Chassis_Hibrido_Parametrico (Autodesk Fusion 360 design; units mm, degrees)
part number: 2026-10-27-14-45-14-391
part number: 2026-10-27-14-47-23-326
part number: 2026-10-27-14-47-50-998
part number: 2026-10-27-14-47-52-763
part number: 2026-10-27-14-47-55-088
parameter "comprimento" = 1706
parameter "largura" = 1146
parameter "altura" = 460
parameter "d_furo_susp" = 101.6
parameter "x_furo_susp" = 657
parameter "z_furo_susp" = 218
parameter "folga_furo_susp" = 40
parameter "espessura_furo_susp" = 26
parameter "ang_chamfro_susp" = 30
parameter "tamanho_susp" = 181.6 (= "d_furo_susp + 2 * folga_furo_susp")
parameter "dist_susp" = 521.1667 (= "x_furo_susp - tamanho_susp / 2 - chanfro_susp")
parameter "chanfro_susp" = 45.0333 (= "espessura_furo_susp / tan(ang_chamfro_susp)")
parameter "comp_tras" = 194
parameter "degrau_tras" = 16.5
parameter "recuo_rampa_tras" = 38
parameter "ang_rampa_tras" = 20.56
parameter "alt_aresta_tras" = 384.9877 (= "altura - degrau_tras - ( comp_tras - recuo_rampa_tras ) * tan(ang_rampa_tras)")
parameter "base_torre" = 320
parameter "alt_torre" = 304
parameter "alt_torre_frente" = 279.5 (= "alt_torre - queda_topo_torre")
parameter "alt_ombro_torre" = 191.5
parameter "x_ombro_torre" = 159.5
parameter "recuo_ombro_torre" = 8.5
parameter "dif_topo_torre" = 88 (= "alt_torre_frente - alt_ombro_torre")
parameter "larg_tras_torre" = 158
parameter "dist_suporte_braco" = 70
parameter "larg_suporte_braco" = 220
parameter "alt_suporte_braco" = 16
parameter "base_suporte_braco" = 40
parameter "esp_suporte_braco" = 210
parameter "esp_parede_braco" = 20 (= "esp_suporte_braco * rel_parede_braco")
parameter "d_furo_ponta" = 110
parameter "parede_ponta" = 24
parameter "r_ext_ponta" = 79 (= "d_furo_ponta / 2 + parede_ponta")
parameter "x_ponta" = 68
parameter "y_ponta" = 16
parameter "margem_ponta" = 5
parameter "comp_ponta" = 152 (= "x_ponta + r_ext_ponta + margem_ponta")
parameter "esp_ponta_frente" = 63
parameter "esp_ponta_tras" = 45
parameter "ang_ponta_tras" = 97
parameter "offset_topo_ponta" = 6
parameter "ang_ponta_planta" = 100
parameter "furo_ponta" = 20 (= "d_furo_ponta * 0.0909090909090909 * 2")
parameter "comp_box" = 320.88 (= "largura * 0.28")
parameter "alt_box" = 170.016 (= "altura * 0.3696")
parameter "topo_box" = 214.6366 (= "comp_box * 0.6689")
parameter "alt_tras_box" = 105.0019 (= "alt_box * 0.6176")
parameter "larg_box" = 305.0328 (= "comprimento * 0.1788")
parameter "x_box" = -50
parameter "dist_torres" = 810 (= "largura - 2 * larg_tras_torre - 20 mm")
parameter "meio_viga" = 380 (= "( dist_torres - 50 mm ) / 2")
parameter "reto_sup_viga" = 130 (= "meio_viga * 130 / 380")
parameter "reto_inf_viga" = 105 (= "meio_viga * 105 / 380")
parameter "esp_fundo_braco" = 4.955 comment "fundo do suporte do braco"
parameter "queda_topo_torre" = 24.5 comment "diferenca entre alt_torre e alt_torre_frente"
derived_base_feature "Derived Base Feature1" bodies "camara", "camara (Assembly_Perseverance)"
derived_base_feature "Derived Base Feature2" bodies "lente_dir", "lente_dir (Assembly_Perseverance)"
derived_base_feature "Derived Base Feature3" bodies "sensor_esq", "sensor_esq (Assembly_Perseverance)"
derived_base_feature "Derived Base Feature4" bodies "lente_esq", "lente_esq (Assembly_Perseverance)"
derived_base_feature "Derived Base Feature5" bodies "sensor_dir (Assembly_Perseverance)"
derived_base_feature "Derived Base Feature6" bodies "Body1 (Assembly_Perseverance)"
sketch "Sketch1" plane through (0, 0, 0) normal (0, 0, 1) x axis (1, 0, 0)
  line L1 (-853, 573) -> (853, 573)
  line L2 (-853, -573) -> (-853, 573)
  line L3 (853, -573) -> (-853, -573)
  line L4 (853, 573) -> (853, -573)
  line L5 (-853, -573) -> (853, 573)
  line L6 (853, -573) -> (-853, 573)
  point P6 (0, 0)
  point P1 (0, 0)
  point P4 (-853, -573)
  point P5 (853, -573)
  point P3 (-853, 573)
  horizontal L1
  perpendicular L1 L2
  parallel L1 L3
  parallel L2 L4
  coincident L5 P6
  coincident L6 P6
  coincident P1 P6
  dimension "d1" distance P4 P5 = 1706 (= "comprimento")
  dimension "d2" distance P3 P4 = 1146 (= "largura")
extrude "Extrude1" new body sketch "Sketch1" profile of L1 L2 L3 L4 along normal blind 460 (= "altura")
sketch "Sketch2" plane through (0, 0, 460) normal (0, 0, 1) x axis (-1, 0, 0)
  line L1 (-853, -573) -> (-853, 573)
  line L2 (853, -573) -> (-853, -573)
  line L3 (853, 573) -> (853, -573)
  line L4 (-853, 573) -> (853, 573)
  line L5 (331.8333, 573) -> (853, 573)
  line L6 (286.8, 599) -> (331.8333, 573)
  line L7 (105.2, 599) -> (286.8, 599)
  line L8 (105.2, 573) -> (105.2, 599)
  line L9 (105.2, 573) -> (331.8333, 573)
  point P5 (853, 573)
  point P6 (853, 573)
  point P7 (331.8333, 573)
  point P10 (105.2, 573)
  point P8 (286.8, 599)
  point P9 (105.2, 599)
  coincident P5 P6
  coincident L4 P7
  parallel L4 L7
  coincident L4 P10
  perpendicular L4 L8
  dimension "d5" distance P6 P7 = 521.1667 (= "dist_susp")
  dimension "d6" distance P7 P8 = 45.0333 (= "chanfro_susp")
  dimension "d7" distance L7 L9 = 26 (= "espessura_furo_susp")
  dimension "d8" distance P8 P9 = 181.6 (= "tamanho_susp")
extrude "Extrude2" add sketch "Sketch2" profile of L4 L6 L7 L8 L9 no distance stored
sketch "Sketch3" plane through (0, -573, 0) normal (0, -1, 0) x axis (1, 0, 0)
  line L1 (-105.2, 0) -> (-105.2, 460)
  line L2 (853, 0) -> (-105.2, 0)
  line L3 (853, 460) -> (853, 0)
  line L4 (-105.2, 460) -> (853, 460)
  line L5 (1047, 460) -> (853, 460)
  line L6 (1047, 75.0123) -> (1047, 460)
  line L7 (891, 16.5) -> (1047, 75.0123)
  line L8 (853, 16.5) -> (891, 16.5)
  line L9 (853, 16.5) -> (853, 460)
  point P5 (853, 460)
  point P6 (853, 460)
  point P10 (853, 16.5)
  point P7 (1047, 460)
  point P8 (1047, 75.0123)
  point P4 (853, 0)
  point P9 (891, 16.5)
  coincident P5 P6
  perpendicular L3 L5
  perpendicular L5 L6
  coincident L3 P10
  perpendicular L3 L8
  dimension "d8" distance P5 = 181.6 (= "tamanho_susp")
  dimension "d11" distance P6 P7 = 194 (= "comp_tras")
  dimension "d12" distance P7 P8 = 384.9877 (= "alt_aresta_tras")
  dimension "d13" distance P4 L8 = 16.5 (= "degrau_tras")
  dimension "d14" distance P9 P10 = 38 (= "recuo_rampa_tras")
extrude "Extrude3" add sketch "Sketch3" profile of L3 L5 L6 L7 L8 L9 no distance stored
sketch "Sketch4" plane through (0, -573, 0) normal (0, -1, 0) x axis (1, 0, 0)
  line L1 (-105.2, 0) -> (-105.2, 460)
  line L2 (853, 0) -> (-105.2, 0)
  line L3 (853, 16.5) -> (853, 0)
  line L4 (-105.2, 460) -> (1047, 460)
  line L5 (1047, 764) -> (1047, 460)
  line L6 (895, 739.5) -> (1047, 764)
  line L7 (895, 651.5) -> (895, 739.5)
  line L8 (886.5, 651.5) -> (895, 651.5)
  line L9 (727, 460) -> (886.5, 651.5)
  line L10 (727, 460) -> (1047, 460)
  line L11 (891, 16.5) -> (853, 16.5)
  line L12 (1047, 75.0123) -> (891, 16.5)
  line L13 (1047, 460) -> (1047, 75.0123)
  point P6 (1047, 460)
  point P7 (1047, 460)
  point P12 (727, 460)
  point P13 (1047, 460)
  point P8 (1047, 764)
  point P11 (886.5, 651.5)
  point P10 (895, 651.5)
  point P9 (895, 739.5)
  coincident P6 P7
  perpendicular L4 L5
  parallel L5 L7
  perpendicular L7 L8
  coincident L4 P12
  coincident P6 P13
  dimension "d17" distance P7 P8 = 304 (= "alt_torre")
  dimension "d18" distance P12 P13 = 320 (= "base_torre")
  dimension "d19" distance P11 P12 = 159.5 (= "x_ombro_torre")
  dimension "d20" distance L8 L10 = 191.5 (= "alt_ombro_torre")
  dimension "d21" distance P10 P11 = 8.5 (= "recuo_ombro_torre")
  dimension "d22" distance P9 P10 = 88 (= "dif_topo_torre")
extrude "Extrude4" add sketch "Sketch4" profile of L4 L5 L6 L7 L8 L9 L10 to an object
mirror "Mirror1" mirrorStitchTolerance 0.1
mirror "Mirror2" mirrorStitchTolerance 0.1
mirror "Mirror3" mirrorStitchTolerance 0.1
sketch "Sketch6" plane through (0, 573, 0) normal (0, 1, 0) x axis (-1, 0, 0)
  line L1 (105.2, 460) -> (105.2, 0)
  line L2 (-727, 460) -> (105.2, 460)
  line L3 (-886.5, 651.5) -> (-727, 460)
  line L4 (-895, 651.5) -> (-886.5, 651.5)
  line L5 (-895, 739.5) -> (-895, 651.5)
  line L6 (-1047, 764) -> (-895, 739.5)
  line L7 (-1047, 75.0123) -> (-1047, 764)
  line L8 (-891, 16.5) -> (-1047, 75.0123)
  line L9 (-853, 16.5) -> (-891, 16.5)
  line L10 (-853, 0) -> (-853, 16.5)
  line L11 (105.2, 0) -> (-853, 0)
  line L12 (-1047, 651.5) -> (-895, 651.5)
  point P6 (-895, 651.5)
  point P13 (-895, 651.5)
  point P14 (-1047, 651.5)
  coincident P6 P13
  coincident L7 P14
  perpendicular L7 L12
extrude "Extrude6" add sketch "Sketch6" profile of L5 L6 L7 L12 along normal blind 10
sketch "Sketch7" plane through (0, 415, 0) normal (0, -1, 0) x axis (1, 0, 0)
  line L1 (1047, 764) -> (1047, 75.0123)
  line L2 (895, 739.5) -> (1047, 764)
  line L3 (895, 651.5) -> (895, 739.5)
  line L4 (886.5, 651.5) -> (895, 651.5)
  line L5 (727, 460) -> (886.5, 651.5)
  line L6 (853, 460) -> (727, 460)
  line L7 (1047, 651.5) -> (895, 651.5)
  line L8 (853, 16.5) -> (853, 460)
  line L9 (891, 16.5) -> (853, 16.5)
  line L10 (1047, 75.0123) -> (891, 16.5)
  point P6 (895, 651.5)
  point P9 (895, 651.5)
  point P10 (1047, 651.5)
  coincident P6 P9
  coincident L1 P10
  perpendicular L1 L7
extrude "Extrude7" add sketch "Sketch7" profile of L1 L2 L3 L7 along normal blind 10
sketch "Sketch8" plane through (1047, 0, 0) normal (1, 0, 0) x axis (0, 1, 0)
  line L1 (405, 764) -> (583, 764)
  line L2 (405, 651.5) -> (405, 764)
  line L3 (415, 651.5) -> (405, 651.5)
  line L4 (415, 75.0123) -> (415, 651.5)
  line L5 (573, 651.5) -> (573, 75.0123)
  line L6 (583, 651.5) -> (573, 651.5)
  line L7 (583, 764) -> (583, 651.5)
  line L8 (573, 651.5) -> (415, 651.5)
  line L9 (573, 75.0123) -> (415, 75.0123)
  point P5 (415, 651.5)
  point P10 (415, 651.5)
  point P8 (573, 651.5)
  point P11 (573, 651.5)
  coincident P5 P10
  coincident P8 P11
extrude "Extrude8" add sketch "Sketch8" profile of L1 L2 L3 L6 L7 L8 along normal blind 10
mirror "Mirror4" mirrorStitchTolerance 0.1
sketch "Sketch9" plane through (0, 405, 0) normal (0, -1, 0) x axis (1, 0, 0)
  line L1 (1057, 651.5) -> (895, 651.5)
  line L2 (1057, 764) -> (1057, 651.5)
  line L3 (1047, 764) -> (1057, 764)
  line L4 (895, 739.5) -> (1047, 764)
  line L5 (895, 651.5) -> (895, 739.5)
  line L6 (934.6634, 666.5679) -> (910.38, 733.2861)
  line L7 (916.0182, 735.3382) -> (910.38, 733.2861)
  line L8 (895, 739.5) -> (910.38, 733.2861)
  line L9 (895, 733.2861) -> (910.38, 733.2861)
  line L10 (940.3016, 668.62) -> (916.0182, 735.3382)
  line L11 (934.6634, 666.5679) -> (940.3016, 668.62)
  line L12 (1025.8136, 699.7439) -> (1001.5302, 766.462)
  line L13 (1001.5302, 766.462) -> (995.892, 764.4099)
  line L14 (1020.1755, 697.6917) -> (995.892, 764.4099)
  line L15 (1020.1755, 697.6917) -> (1025.8136, 699.7439)
  line L16 (1023.2485, 689.2486) -> (1020.1755, 697.6917)
  line L17 (1028.8867, 691.3007) -> (1023.2485, 689.2486)
  line L18 (1025.8136, 699.7439) -> (1028.8867, 691.3007)
  point P6 (895, 739.5)
  point P10 (895, 739.5)
  point P11 (895, 733.2861)
  point P7 (910.38, 733.2861)
  point P9 (916.0182, 735.3382)
  point P8 (934.6634, 666.5679)
  point P16 (1020.1755, 697.6917)
  point P17 (1023.2485, 689.2486)
  point P18 (1028.8867, 691.3007)
  perpendicular L6 L7
  coincident P6 P10
  coincident L5 P11
  perpendicular L5 L9
  perpendicular L7 L10
  perpendicular L10 L11
  perpendicular L15 L16
  perpendicular L16 L17
  dimension "d43" distance P7 P9 = 6
  dimension "d44" distance L5 P7 = 15.38
  dimension "d45" angle L8 L9 = 22
  dimension "d46" angle L6 L9 = 110
  dimension "d47" distance P7 P8 = 71
  dimension "d60" distance P16 P17 = 8.985
  dimension "d61" distance P17 P18 = 6
  dimension "d54" R-Pattern1-uDistance = -91
  dimension "d55" R-Pattern1-vDistance = 0
extrude "Extrude9" add sketch "Sketch9" profile of L4 L6 L7 L10 L11 L12 L14 L15 L16 L17 L18 along normal blind 20
mirror "Mirror5" mirrorStitchTolerance 0.1
fillet "Fillet2" radius 15 15 15
work_plane "WorkPlane1" ExtraOffset 0
sketch "Sketch11" plane through (-783, 0, 0) normal (-1, 0, 0) x axis (0, -1, 0)
  line L1 (-793, 460) -> (-573, 16)
  line L2 (-573, 460) -> (-793, 460)
  line L3 (-613, 16) -> (-573, 16)
  line L4 (-613, 96.7273) -> (-613, 16)
  line L5 (-573, 16) -> (-573, 460)
  line L6 (-573, 460) -> (573, 460)
  line L7 (573, 0) -> (-573, 0)
  point P5 (-613, 96.7273)
  point P7 (-573, 460)
  point P8 (-573, 460)
  point P2 (-573, 16)
  point P4 (-613, 16)
  point P3 (-793, 460)
  coincident L1 P5
  perpendicular L3 L4
  perpendicular L3 L5
  coincident P7 P8
  horizontal L2
  vertical L5
  dimension "d111" distance P2 P4 = 40 (= "base_suporte_braco")
  dimension "d147" distance P2 L7 = 16 (= "alt_suporte_braco")
  dimension "d148" distance P3 P8 = 220 (= "larg_suporte_braco")
extrude "Extrude16" new body sketch "Sketch11" profile of L1 L2 L5 no distance stored
work_plane "WorkPlane2" AlongDistance 200 (= "larg_suporte_braco - esp_parede_braco") ExtraOffset 0
sketch "Sketch12" plane through (0, 773, 0) normal (0, 1, 0) x axis (1, 0, 0)
  line L1 (-783, -460) -> (-783, -16)
  line L2 (-573, -460) -> (-783, -460)
  line L3 (-573, -16) -> (-573, -460)
  line L4 (-593, -16) -> (-593, -36)
  line L5 (-763, -16) -> (-763, -36)
  line L6 (-783, -16) -> (-573, -16)
  line L7 (-763, -440) -> (-763, -36)
  line L8 (-593, -440) -> (-763, -440)
  line L9 (-593, -36) -> (-593, -440)
  line L10 (-763, -36) -> (-593, -36)
  point P9 (-593, -36)
  point P13 (-593, -36)
  point P10 (-593, -16)
  point P6 (-763, -36)
  point P12 (-763, -36)
  point P11 (-763, -16)
  coincident P9 P13
  coincident P10 L6
  vertical L4
  coincident P6 P12
  coincident P11 L6
  vertical L5
extrude "Extrude17" cut sketch "Sketch12" profile of L9 L7 L8 L4 L5 L6 L10 no distance stored
mirror "Mirror9" mirrorStitchTolerance 0.1
combine "Combine1"
work_plane "WorkPlane3" AlongDistance -6 ExtraOffset 0
sketch "Sketch13" plane through (0, 577, 0) normal (0, 1, 0) x axis (1, 0, 0)
  line L1 (1209, -758) -> (1057, -758)
  line L2 (1214.4841, -713.3354) -> (1209, -758)
  line L3 (1057, -695) -> (1214.4841, -713.3354)
  line L4 (1057, -764) -> (1057, -651.5)
  point P2 (1057, -758)
  point P5 (1057, -695)
  point P3 (1209, -758)
  point P4 (1214.4841, -713.3354)
  point P7 (1057, -764)
  horizontal L1
  coincident P2 L4
  coincident P5 L4
  dimension "d124" distance P2 P5 = 63 (= "esp_ponta_frente")
  dimension "d125" distance P2 P3 = 152 (= "comp_ponta")
  dimension "d127" distance P3 P4 = 45 (= "esp_ponta_tras")
  dimension "d128" angle L1 L2 = 97 (= "ang_ponta_tras")
  dimension "d151" distance L1 P7 = 6 (= "offset_topo_ponta")
extrude "Extrude18" add sketch "Sketch13" no distance stored
sketch "Sketch14" plane through (0, 0, 758) normal (0, 0, 1) x axis (-1, 0, 0)
  line L1 (-1057, -577) -> (-1209, -577)
  line L2 (-1209, -419) -> (-1057, -419)
  line L3 (-1209, -577) -> (-1209, -419)
  line L4 (-1144.71, -434.4656) -> (-1057, -419)
  line L5 (-1057, -577) -> (-1117.6904, -587.7014)
  line L6 (-1117.6904, -587.7014) -> (-1144.71, -434.4656)
  line L7 (-2763, -419) -> (-1057, -419)
  line L8 (-2763, -1723) -> (-2763, -419)
  line L9 (-1057, -1723) -> (-2763, -1723)
  line L10 (-1057, -577) -> (-1057, -1723)
  line L11 (-1057, -419) -> (-1057, -577)
  line L12 (-1057, -405) -> (-1057, -583)
  arc A1 centre (-1131.2002, -511.0835) radius 77.7998 clockwise from (-1117.6904, -587.7014) to (-1144.71, -434.4656)
  point P4 (-1057, -419)
  point P6 (-1057, -419)
  point P3 (-1057, -577)
  point P10 (-1057, -577)
  point P14 (-1057, -577)
  point P13 (-1057, -1723)
  point P11 (-2763, -419)
  coincident P4 P6
  tangent L4 A1
  coincident P3 P10
  tangent A1 L5
  perpendicular L4 L6
  tangent L3 A1
  perpendicular L7 L8
  perpendicular L8 L9
  coincident P3 P14
  perpendicular L1 L10
  horizontal L7
  dimension "d152" angle L4 L12 = 100
  dimension "d229" distance P13 P14 = 1146 (= "largura")
  dimension "d230" distance P6 P11 = 1706 (= "comprimento")
extrude "Extrude19" cut sketch "Sketch14" profile of L1 L2 L3 L4 A1 L5 L7 L8 L9 L10 L12 no distance stored
extrude "Extrude20" add sketch "Sketch14" profile of L1 A1 L5 to an object
sketch "Sketch15" plane through (0, 0, 758) normal (0, 0, 1) x axis (-1, 0, 0)
  line L1 (-1144.71, -434.4656) -> (-1057, -419)
  line L2 (-1057, -577) -> (-1117.6904, -587.7014)
  line L3 (-1057, -419) -> (-1057, -577)
  arc A1 centre (-1131.2002, -511.0835) radius 77.7998 clockwise from (-1117.6904, -587.7014) to (-1144.71, -434.4656)
  circle C1 centre (-1131.2002, -511.0835) radius 55
  concentric A1 C1
  dimension "d136" diameter C1 = 110 (= "d_furo_ponta")
extrude "Extrude21" cut sketch "Sketch15" profile of C1 no distance stored
fillet "Fillet3" radius 10 (= "furo_ponta / 2")
mirror "Mirror8" mirrorStitchTolerance 0.1
sketch "Sketch18" plane through (0, 0, 758) normal (0, 0, 1) x axis (-1, 0, 0)
  line L1 (-1144.71, -434.4656) -> (-1057, -419)
  line L2 (-1057, -577) -> (-1117.6904, -587.7014)
  line L3 (-1057, -419) -> (-1057, -577)
  line L4 (-1021.2002, -511.0835) -> (-1131.2002, -511.0835)
  line L5 (-1186.2002, -415.8207) -> (-1131.2002, -511.0835)
  line L6 (-1186.2002, -606.3463) -> (-1131.2002, -511.0835)
  line L7 (-1201.2582, -426.2786) -> (-1182.7994, -452.8569)
  line L8 (-1169.6144, -408.009) -> (-1155.8263, -437.284)
  line L9 (-1182.7994, -569.3101) -> (-1201.2582, -595.8884)
  line L10 (-1155.8263, -584.883) -> (-1169.6144, -614.158)
  circle C1 centre (-1131.2002, -511.0835) radius 110
  circle C2 centre (-1186.2002, -415.8207) radius 18.3333
  circle C3 centre (-1186.2002, -606.3463) radius 18.3333
  circle C4 centre (-1021.2002, -511.0835) radius 18.3333
  circle C5 centre (-1131.2002, -511.0835) radius 55
  arc A1 centre (-1131.2002, -511.0835) radius 77.7998 clockwise from (-1117.6904, -587.7014) to (-1144.71, -434.4656)
  point P6 (-1131.2002, -511.0835)
  point P7 (-1131.2002, -511.0835)
  point P8 (-1021.2002, -511.0835)
  point P9 (-1186.2002, -415.8207)
  point P10 (-1186.2002, -606.3463)
  point P11 (-1186.2002, -415.8207)
  point P12 (-1186.2002, -606.3463)
  point P13 (-1021.2002, -511.0835)
  point P15 (-1201.2582, -426.2786)
  point P17 (-1169.6144, -408.009)
  point P18 (-1201.2582, -595.8884)
  point P20 (-1169.6144, -614.158)
  point P21 (-1155.8263, -584.883)
  point P19 (-1182.7994, -569.3101)
  point P14 (-1182.7994, -452.8569)
  point P16 (-1155.8263, -437.284)
  concentric C1 C5
  coincident P6 P7
  coincident C1 P8
  horizontal L4
  coincident C1 P9
  coincident C1 P10
  coincident P9 P11
  coincident P10 P12
  coincident P8 P13
  coincident C2 P15
  coincident C1 P15
  tangent C2 L7
  coincident C2 P17
  coincident C1 P17
  tangent C2 L8
  coincident C1 P18
  coincident C3 P18
  tangent C3 L9
  coincident C1 P20
  coincident C3 P20
  tangent C3 L10
  coincident P21 A1
  coincident P19 A1
  coincident P14 A1
  coincident P16 A1
  dimension "d153" diameter C1 = 220 (= "d_furo_ponta * 2")
  dimension "d154" angle L4 L5 = 120
  dimension "d155" angle L4 L6 = 120
  dimension "d225" diameter C3 = 36.6667 (= "d_furo_ponta / 3")
  dimension "d226" diameter C2 = 36.6667 (= "d_furo_ponta / 3")
  dimension "d227" diameter C4 = 36.6667 (= "d_furo_ponta / 3")
extrude "Extrude24" add sketch "Sketch18" profile of C1 C2 C3 C4 L7 L8 L9 L10 against normal blind 20
extrude "Extrude25" add sketch "Sketch18" profile of C1 C2 C3 C4 along normal blind 15
sketch "Sketch19" plane through (0, -599, 0) normal (0, -1, 0) x axis (1, 0, 0)
  line L1 (-286.8, 0) -> (-286.8, 460)
  line L2 (-105.2, 0) -> (-286.8, 0)
  line L3 (-105.2, 460) -> (-105.2, 0)
  line L4 (-853, 460) -> (-853, 0)
  line L5 (-286.8, 460) -> (-105.2, 460)
  circle C1 centre (-196, 218) radius 50.8
  point P6 (-196, 218)
  dimension "d160" diameter C1 = 101.6 (= "d_furo_susp")
  dimension "d161" distance L2 P6 = 218 (= "z_furo_susp")
  dimension "d162" distance P6 L4 = 657 (= "x_furo_susp")
extrude "Extrude26" cut sketch "Sketch19" profile of C1 against normal blind 97
work_plane "WorkPlane4"
mirror "Mirror10" mirrorStitchTolerance 0.1
sketch "Sketch20" plane through (0, 0, 460) normal (0, 0, 1) x axis (-1, 0, 0)
  line L1 (783, -573) -> (783, -793)
  line L2 (853, -573) -> (783, -573)
  line L3 (853, 573) -> (853, -573)
  line L4 (783, 573) -> (853, 573)
  line L5 (783, 793) -> (783, 573)
  line L6 (573, 793) -> (783, 793)
  line L7 (573, 573) -> (573, 793)
  line L8 (331.8333, 573) -> (573, 573)
  line L9 (286.8, 599) -> (331.8333, 573)
  line L10 (105.2, 599) -> (286.8, 599)
  line L11 (105.2, 573) -> (105.2, 599)
  line L12 (-727, 573) -> (105.2, 573)
  line L13 (-727, 415) -> (-727, 573)
  line L14 (-853, 415) -> (-727, 415)
  line L15 (-853, -415) -> (-853, 415)
  line L16 (-727, -415) -> (-853, -415)
  line L17 (-727, -573) -> (-727, -415)
  line L18 (105.2, -573) -> (-727, -573)
  line L19 (105.2, -599) -> (105.2, -573)
  line L20 (286.8, -599) -> (105.2, -599)
  line L21 (331.8333, -573) -> (286.8, -599)
  line L22 (573, -573) -> (331.8333, -573)
  line L23 (573, -793) -> (573, -573)
  line L24 (783, -793) -> (573, -793)
  line L25 (-250.7128, 160) -> (-185.3, 573)
  line L26 (-458.4, 0) -> (-277.0131, 119.2505)
  line L27 (-1.2664, 50) -> (-85.3, 573)
  line L28 (0, 0) -> (0, 34.1359)
  line L29 (-458.4, 0) -> (0, 0)
  line L30 (0, 0) -> (0, -34.1359)
  line L31 (-1.2664, -50) -> (-85.3, -573)
  line L32 (-250.7128, -160) -> (-185.3, -573)
  line L33 (-458.4, 0) -> (-277.0131, -119.2505)
  arc A1 centre (-100, 34.1359) radius 100 clockwise from (-1.2664, 50) to (0, 34.1359)
  arc A2 centre (-309.9741, 169.3861) radius 60 clockwise from (-250.7128, 160) to (-277.0131, 119.2505)
  arc A3 centre (-100, -34.1359) radius 100 clockwise from (0, -34.1359) to (-1.2664, -50)
  arc A4 centre (-309.9741, -169.3861) radius 60 clockwise from (-277.0131, -119.2505) to (-250.7128, -160)
  point P26 (-185.3, 573)
  point P28 (-85.3, 573)
  point P1 (0, 0)
  point P29 (0, 0)
  point P41 (-185.3, -573)
  point P27 (-458.4, 0)
  point P45 (-458.4, 0)
  point P40 (-85.3, -573)
  point P37 (0, 0)
  point P30 (-1.2664, 50)
  point P39 (-1.2664, -50)
  point P31 (0, 34.1359)
  point P36 (0, -34.1359)
  point P33 (-250.7128, 160)
  point P42 (-250.7128, -160)
  point P34 (-277.0131, 119.2505)
  point P44 (-277.0131, -119.2505)
  coincident L12 P26
  coincident L12 P28
  coincident P1 P29
  vertical L28
  horizontal L29
  tangent L27 A1
  tangent L28 A1
  tangent L25 A2
  tangent L26 A2
  symmetric P26 L29 P41
  symmetric P27 L29 P45
  symmetric P28 L29 P40
  symmetric P29 L29 P37
  symmetric L29 P30 P39
  symmetric L29 P31 P36
  symmetric L29 A1 A3
  symmetric L29 P33 P42
  symmetric L29 P34 P44
  symmetric L29 A2 A4
  dimension "d167" radius A1 = 100
  dimension "d168" radius A2 = 60
  dimension "d228" distance P26 P28 = 100 (= "comprimento / 17.06")
  dimension "d77" distance L3 P40 = 938.3 (= "comprimento * 0.55")
  dimension "d78" distance L18 P39 = 523 (= "largura / 2 - 50 mm")
  dimension "d79" distance P41 P42 = 413 (= "largura / 2 - 160 mm")
  dimension "d80" distance P37 P45 = 458.4 (= "largura / 2.5")
  dimension "d81" angle L12 L25 = 99
extrude "Extrude27" add sketch "Sketch20" profile of L12 L18 L25 L26 L27 L28 A1 A2 L30 A3 L31 L32 A4 L33 along normal blind 10
extrude "Extrude28" add of existing geometry blind 8.828
fillet "Fillet6" radius 25
sketch "Sketch1" plane through (0, 0, 0) normal (0, 1, 0) x axis (1, 0, 0)
  line L1 (320.88, 0) -> (0, 0)
  line L2 (320.88, -105.0019) -> (320.88, 0)
  line L3 (214.6366, -170.016) -> (320.88, -105.0019)
  line L4 (0, -170.016) -> (214.6366, -170.016)
  line L5 (0, 0) -> (0, -170.016)
  point P1 (0, 0)
  point P2 (0, 0)
  point P6 (0, -170.016)
  point P5 (214.6366, -170.016)
  point P3 (320.88, 0)
  point P4 (320.88, -105.0019)
  coincident P1 P2
  horizontal L1
  perpendicular L1 L2
  parallel L1 L4
  vertical L5
  dimension "d1_1" distance P2 P6 = 170.016 (= "alt_box")
  dimension "d2_1" distance P5 P6 = 214.6366 (= "topo_box")
  dimension "d3_1" distance P2 P3 = 320.88 (= "comp_box")
  dimension "d4_1" distance P3 P4 = 105.0019 (= "alt_tras_box")
extrude "Extrude1" new body sketch "Sketch1" along normal blind 305.0328 (= "larg_box") named "d5_1"
work_plane "WorkPlane1" AlongDistance -25 named "d7_1" ExtraOffset 0 named "d8_1"
sketch "Sketch2" plane through (0, 280.0328, 0) normal (0, 1, 0) x axis (1, 0, 0)
  line L1 (0, 0) -> (0, -170.016)
  line L2 (-55, -170.016) -> (0, -170.016)
  line L3 (0, -115.016) -> (-55, -170.016)
  point P2 (0, -170.016)
  point P4 (0, -170.016)
  point P6 (0, -115.016)
  point P5 (-55, -170.016)
  coincident P2 P4
  perpendicular L1 L2
  coincident L1 P6
  dimension "d9_1" distance P4 P5 = 55
  dimension "d10_1" distance P4 P6 = 55
extrude "Extrude2" new body sketch "Sketch2" against normal blind 55 named "d11_1"
work_plane "WorkPlane2" AlongDistance 55 named "d13_1" ExtraOffset 0 named "d14_1"
sketch "Sketch3" plane through (-55, 0, 0) normal (-1, 0, 0) x axis (0, -1, 0)
  line L1 (-280.0328, 115.016) -> (-280.0328, 170.016)
  line L2 (-225.0328, 115.016) -> (-280.0328, 115.016)
  line L3 (-225.0328, 170.016) -> (-225.0328, 115.016)
  line L4 (-280.0328, 170.016) -> (-225.0328, 170.016)
  line L5 (-275.0328, 120.016) -> (-275.0328, 165.016)
  line L6 (-230.0328, 120.016) -> (-275.0328, 120.016)
  line L7 (-230.0328, 165.016) -> (-230.0328, 120.016)
  line L8 (-275.0328, 165.016) -> (-230.0328, 165.016)
  dimension "d15_1" = -5
extrude "Extrude3" cut sketch "Sketch3" profile of L5 L6 L7 L8 against normal blind 50 named "d16_1"
sketch "Sketch4" plane through (0, 0, 170.016) normal (0, 0, 1) x axis (-1, 0, 0)
  line L1 (55, -280.0328) -> (0, -280.0328)
  line L2 (55, -225.0328) -> (55, -280.0328)
  line L3 (0, -225.0328) -> (55, -225.0328)
  line L4 (0, -280.0328) -> (0, -225.0328)
  line L5 (0, -225.0328) -> (55, -280.0328)
  circle C1 centre (27.5, -252.5328) radius 25
  point P3 (55, -280.0328)
  point P6 (55, -280.0328)
  point P5 (0, -225.0328)
  point P7 (0, -225.0328)
  point P8 (27.5, -252.5328)
  coincident P3 P6
  coincident P5 P7
  midpoint L5 P8
  dimension "d18_1" diameter C1 = 50
extrude "Extrude4" new body sketch "Sketch4" profile of C1 along normal blind 5 named "d19_1"
sketch "Sketch5" plane through (0, 0, 175.016) normal (0, 0, 1) x axis (-1, 0, 0)
  circle C1 centre (27.5, -252.5328) radius 25
  circle C2 centre (27.5, -252.5328) radius 15
  concentric C1 C2
  dimension "d21_1" diameter C2 = 30
extrude "Extrude5" add sketch "Sketch5" profile of C2 along normal blind 10 named "d22_1"
sketch "Sketch6" plane through (0, 0, 185.016) normal (0, 0, 1) x axis (-1, 0, 0)
  circle C1 centre (27.5, -252.5328) radius 15
  circle C2 centre (27.5, -252.5328) radius 6.25
  concentric C1 C2
  dimension "d24_1" diameter C2 = 12.5
extrude "Extrude6" add sketch "Sketch6" profile of C2 along normal blind 70 named "d25_1"
chamfer "Chamfer1" distance 2 named "d27_1"
sketch "Sketch7" plane through (0, 0, 0) normal (0, 0, -1) x axis (1, 0, 0)
  line L1 (0, 0) -> (320.88, 0)
  line L2 (0, -305.0328) -> (0, 0)
  line L3 (320.88, -305.0328) -> (0, -305.0328)
  line L4 (320.88, 0) -> (320.88, -305.0328)
  line L5 (273.38, -305.0328) -> (320.88, -305.0328)
  line L6 (273.38, -277.5328) -> (273.38, -305.0328)
  line L7 (320.88, -277.5328) -> (273.38, -277.5328)
  line L8 (320.88, -305.0328) -> (320.88, -277.5328)
  point P5 (320.88, -305.0328)
  point P6 (320.88, -305.0328)
  point P7 (273.38, -305.0328)
  point P9 (320.88, -277.5328)
  horizontal L5
  vertical L6
  horizontal L7
  vertical L8
  coincident P5 P6
  dimension "d28_1" distance P6 P7 = 47.5
  dimension "d29_1" distance P6 P9 = 27.5
  dimension "d13_3" angle P7 = 162 (= "180 deg - 18 deg")
extrude "Extrude7" cut sketch "Sketch7" profile of L3 L4 L5 L6 L7 L8 against normal blind 230 named "d30_1"
fillet "Fillet1" radius 2
sketch "Sketch3" plane through (0, 0, 0) normal (0, 1, 0) x axis (1, 0, 0)
  line L1 (-102, 0) -> (0, 0)
  line L2 (-102, -209.7618) -> (-102, 0)
  line L3 (0, -242) -> (0, 0)
  arc A1 centre (0, -159.5) radius 82.5 clockwise from (0, -242) to (-58.3197, -217.853)
  arc A2 centre (-102, 0) radius 220 clockwise from (-62.7463, -216.4697) to (-91.5238, -219.7504)
  arc A3 centre (-61.8542, -221.3895) radius 5 clockwise from (-62.7463, -216.4697) to (-58.3197, -217.853)
  arc A4 centre (-92, -209.7618) radius 10 clockwise from (-91.5238, -219.7504) to (-102, -209.7618)
  point P1 (0, 0)
  point P2 (0, 0)
  point P3 (-102, 0)
  point P6 (-102, 0)
  point P4 (0, -242)
  coincident P1 P2
  horizontal L1
  perpendicular L1 L2
  perpendicular A1 L3
  vertical L3
  perpendicular L2 A2
  tangent A1 A3
  tangent A2 A3
  tangent A2 A4
  tangent L2 A4
  coincident P3 P6
  dimension "d10_2" distance P2 P3 = 102 (= "d_furo_ponta - 8 mm")
  dimension "d13_2" distance P2 P4 = 242 (= "d_furo_ponta * 2.2")
  dimension "d73" radius A1 = 82.5 (= "d_furo_ponta * 0.75")
  dimension "d74" radius A2 = 220 (= "d_furo_ponta * 2")
  dimension "d75" radius A3 = 5
  dimension "d76" radius A4 = 10
revolve "Revolve1" sketch "Sketch3" AlongAngle 360 named "d15_2"
sketch "Sketch4" plane through (0, 0, 0) normal (0, 0, -1) x axis (1, 0, 0)
  line L1 (-51, 88.3346) -> (0, 0)
  line L2 (-88.3346, 51) -> (0, 0)
  line L3 (-102, 0) -> (0, 0)
  line L4 (-79.6743, 46) -> (-88.3346, 51)
  line L5 (-46, 79.6743) -> (-51, 88.3346)
  line L6 (-46, -79.6743) -> (-51, -88.3346)
  line L7 (-79.6743, -46) -> (-88.3346, -51)
  line L8 (79.6743, -46) -> (88.3346, -51)
  line L9 (46, -79.6743) -> (51, -88.3346)
  line L10 (46, 79.6743) -> (51, 88.3346)
  line L11 (79.6743, 46) -> (88.3346, 51)
  circle C1 centre (0, 0) radius 102
  arc A1 centre (0, 0) radius 102 clockwise from (-88.3346, 51) to (-51, 88.3346)
  arc A2 centre (0, 0) radius 92 clockwise from (-79.6743, 46) to (-46, 79.6743)
  arc A3 centre (0, 0) radius 102 clockwise from (-51, -88.3346) to (-88.3346, -51)
  arc A4 centre (0, 0) radius 92 clockwise from (-46, -79.6743) to (-79.6743, -46)
  arc A5 centre (0, 0) radius 102 clockwise from (88.3346, -51) to (51, -88.3346)
  arc A6 centre (0, 0) radius 92 clockwise from (79.6743, -46) to (46, -79.6743)
  arc A7 centre (0, 0) radius 102 clockwise from (51, 88.3346) to (88.3346, 51)
  arc A8 centre (0, 0) radius 92 clockwise from (46, 79.6743) to (79.6743, 46)
  point P4 (-51, 88.3346)
  point P3 (-88.3346, 51)
  point P1 (0, 0)
  point P6 (0, 0)
  point P7 (-102, 0)
  point P9 (-46, 79.6743)
  point P8 (-79.6743, 46)
  point P5 (0, 0)
  point P10 (0, 0)
  coincident C1 P4
  coincident C1 P3
  coincident P1 P6
  coincident C1 P7
  horizontal L3
  coincident L1 P9
  coincident L2 P8
  coincident P5 P10
  perpendicular A2 L4
  dimension "d16_2" angle L1 L2 = 30
  dimension "d17_2" angle L2 L3 = 30
  dimension "d18_2" distance A1 A2 = 10
  dimension "d20_2" C-Pattern1-Angle = 360
extrude "Extrude3" add sketch "Sketch4" profile of C1 A1 A2 L4 L5 A3 A4 L6 L7 A5 A6 L8 L9 A7 A8 L10 L11 along normal blind 34 named "d21_2"
sketch "Sketch5" plane through (0, 0, -34) normal (0, 0, -1) x axis (1, 0, 0)
  line L1 (-79.6743, 46) -> (-88.3346, 51)
  line L2 (-51, 88.3346) -> (-46, 79.6743)
  arc A1 centre (0, 0) radius 92 clockwise from (-79.6743, 46) to (-46, 79.6743)
  arc A2 centre (0, 0) radius 102 clockwise from (-88.3346, 51) to (-51, 88.3346)
  circle C1 centre (0, 0) radius 110
  concentric A1 C1
  dimension "d23_2" diameter C1 = 220 (= "d_furo_ponta * 2")
extrude "Extrude4" new body sketch "Sketch5" along normal blind 28 named "d24_2"
work_plane "WorkPlane1" AlongDistance 100 named "d26_2" ExtraOffset 0 named "d27_2"
sketch "Sketch6" plane through (0, 0, -162) normal (0, 0, -1) x axis (-1, 0, 0)
  line L1 (0, -110) -> (0, 0)
  line L2 (95.2628, 55) -> (0, 0)
  line L3 (-95.2628, 55) -> (0, 0)
  circle C1 centre (0, 0) radius 110
  circle C2 centre (95.2628, 55) radius 8
  circle C3 centre (0, -110) radius 8
  circle C4 centre (-95.2628, 55) radius 8
  point P2 (0, 0)
  point P3 (0, 0)
  point P4 (0, -110)
  point P5 (95.2628, 55)
  point P6 (-95.2628, 55)
  point P7 (95.2628, 55)
  point P8 (0, -110)
  point P9 (-95.2628, 55)
  coincident P2 P3
  coincident C1 P4
  vertical L1
  coincident C1 P5
  coincident C1 P6
  coincident P5 P7
  coincident P4 P8
  coincident P6 P9
  equal C2 C3
  equal C3 C4
  dimension "d28_2" angle L1 L2 = 120
  dimension "d29_2" angle L1 L3 = 120
  dimension "d30_2" diameter C3 = 16
extrude "Extrude5" new body sketch "Sketch6" profile of C2 C3 C4 along normal blind 25 named "d31_1"
work_plane "WorkPlane2" AlongDistance -20 named "d40_1" ExtraOffset 0 named "d41_1"
sketch "Sketch7" plane through (0, 0, -182) normal (0, 0, 1) x axis (-1, 0, 0)
  line L1 (6.245, 115) -> (-3.755, 115)
  line L2 (6.245, 105) -> (6.245, 115)
  line L3 (-3.755, 105) -> (6.245, 105)
  line L4 (-3.755, 115) -> (-3.755, 105)
  line L5 (-3.755, 110) -> (0, 110)
  circle C1 centre (0, 110) radius 8
  point P7 (-3.755, 110)
  point P6 (0, 110)
  point P8 (0, 110)
  point P4 (6.245, 105)
  point P2 (-3.755, 115)
  point P5 (-3.755, 105)
  horizontal L1
  vertical L2
  horizontal L3
  vertical L4
  coincident L4 P7
  perpendicular L4 L5
  midpoint L4 P7
  coincident P6 P8
  coincident P4 C1
  dimension "d33_1" distance P2 P5 = 10
  dimension "d34" distance P4 P5 = 10
sketch "Sketch8" plane through (0, 0, -62) normal (0, 0, -1) x axis (1, 0, 0)
  line L1 (0, 110) -> (0, 0)
  line L2 (-37.5, 88) -> (-27.5, 88)
  line L3 (-37.5, 98) -> (-37.5, 88)
  line L4 (-27.5, 98) -> (-37.5, 98)
  line L5 (-27.5, 88) -> (-27.5, 98)
  line L6 (-110, 0) -> (0, 0)
  circle C1 centre (0, 0) radius 110
  point P2 (0, 0)
  point P3 (0, 0)
  point P4 (0, 110)
  point P1 (0, 0)
  point P9 (0, 0)
  point P10 (-110, 0)
  point P5 (-27.5, 88)
  point P6 (-37.5, 88)
  point P8 (-27.5, 98)
  coincident P2 P3
  coincident C1 P4
  vertical L1
  horizontal L2
  vertical L3
  horizontal L4
  vertical L5
  coincident P1 P9
  coincident C1 P10
  perpendicular L1 L6
  dimension "d36_1" distance P5 P6 = 10
  dimension "d37_1" distance P5 P8 = 10
  dimension "d38_1" distance L1 L5 = 27.5 (= "d_furo_ponta * 0.25")
  dimension "d39_1" distance L2 L6 = 88 (= "d_furo_ponta * 0.8")
loft "Loft1" sketch "Sketch8" + "Sketch7"
mirror "Mirror1" mirrorStitchTolerance 0.1 named "d43_1"
circular_pattern "C-Pattern2" TotalAngle 360 named "d51_1"
sketch "Sketch1" plane through (0, 0, 0) normal (0, 1, 0) x axis (1, 0, 0)
  line L1 (-105, 0) -> (0, 0)
  line L2 (-380, 95.6023) -> (-155.1715, 9.2987)
  line L3 (-380, 25.6023) -> (-380, 95.6023)
  line L4 (-155.8562, -45.972) -> (-380, 25.6023)
  line L5 (0, -50) -> (-130, -50)
  line L6 (0, -50) -> (0, 0)
  line L7 (0, -50) -> (130, -50)
  line L8 (155.8562, -45.972) -> (380, 25.6023)
  line L9 (380, 95.6023) -> (155.1715, 9.2987)
  line L10 (105, 0) -> (0, 0)
  line L11 (380, 25.6023) -> (380, 95.6023)
  arc A1 centre (-105, 140) radius 140 clockwise from (-105, 0) to (-155.1715, 9.2987)
  arc A2 centre (-130, 35) radius 85 clockwise from (-130, -50) to (-155.8562, -45.972)
  arc A3 centre (130, 35) radius 85 clockwise from (155.8562, -45.972) to (130, -50)
  arc A4 centre (105, 140) radius 140 clockwise from (155.1715, 9.2987) to (105, 0)
  point P1 (0, 0)
  point P2 (0, 0)
  point P21 (0, 0)
  point P3 (-105, 0)
  point P20 (105, 0)
  point P4 (-155.1715, 9.2987)
  point P17 (155.1715, 9.2987)
  point P6 (-380, 95.6023)
  point P18 (380, 95.6023)
  point P7 (-380, 25.6023)
  point P16 (380, 25.6023)
  point P8 (-155.8562, -45.972)
  point P15 (155.8562, -45.972)
  point P9 (-130, -50)
  point P12 (130, -50)
  point P11 (0, -50)
  point P13 (0, -50)
  coincident P1 P2
  horizontal L1
  tangent L1 A1
  tangent A1 L2
  perpendicular L1 L3
  tangent L4 A2
  perpendicular L3 L5
  perpendicular L1 L6
  tangent A2 L5
  symmetric P2 L6 P21
  symmetric P3 L6 P20
  symmetric P4 L6 P17
  symmetric A1 L6 A4
  symmetric P6 L6 P18
  symmetric P7 L6 P16
  symmetric P8 L6 P15
  symmetric P9 L6 P12
  symmetric A2 L6 A3
  symmetric P11 L6 P13
  dimension "d1_2" distance L3 L6 = 380 (= "( dist_torres - 50 mm ) / 2")
  dimension "d3_2" angle L1 L2 = 159 (= "180 deg - 21 deg")
  dimension "d4_2" distance P2 P3 = 105 (= "reto_inf_viga")
  dimension "d5_2" distance P9 P11 = 130 (= "reto_sup_viga")
  dimension "d7_2" distance P2 P11 = 50
  dimension "d8_3" distance P6 P7 = 70
  dimension "d86" radius A1 = 140
  dimension "d87" radius A2 = 85
work_plane "WorkPlane1" sketch "Sketch1" AlongDistance 105 named "d9_3" ExtraOffset 0 named "d10_3"
sketch "Sketch2" plane through (0, 105, 0) normal (0, 1, 0) x axis (1, 0, 0)
  line L1 (0, -45) -> (0, 0)
  line L2 (105, -45) -> (0, -45)
  line L3 (380, 30.9727) -> (185.3444, -32.2747)
  line L4 (380, 84.3178) -> (380, 30.9727)
  line L5 (165.2583, 14.544) -> (380, 84.3178)
  line L6 (0, 5) -> (105, 5)
  line L7 (0, 5) -> (0, 0)
  line L8 (0, -50) -> (130, -50)
  line L9 (-105, -45) -> (0, -45)
  line L10 (-380, 30.9727) -> (-185.3444, -32.2747)
  line L11 (0, 5) -> (-105, 5)
  line L12 (-165.2583, 14.544) -> (-380, 84.3178)
  line L13 (-380, 84.3178) -> (-380, 30.9727)
  arc A1 centre (105, 215) radius 260 clockwise from (185.3444, -32.2747) to (105, -45)
  arc A2 centre (105, 200) radius 195 clockwise from (165.2583, 14.544) to (105, 5)
  arc A3 centre (-105, 215) radius 260 clockwise from (-105, -45) to (-185.3444, -32.2747)
  arc A4 centre (-105, 200) radius 195 clockwise from (-105, 5) to (-165.2583, 14.544)
  point P1 (0, 0)
  point P2 (0, 0)
  point P3 (0, -45)
  point P15 (0, -45)
  point P4 (105, -45)
  point P16 (-105, -45)
  point P5 (185.3444, -32.2747)
  point P18 (-185.3444, -32.2747)
  point P7 (380, 30.9727)
  point P19 (-380, 30.9727)
  point P8 (380, 84.3178)
  point P24 (-380, 84.3178)
  point P9 (165.2583, 14.544)
  point P23 (-165.2583, 14.544)
  point P10 (105, 5)
  point P20 (-105, 5)
  point P12 (0, 5)
  point P21 (0, 5)
  coincident P1 P2
  vertical L1
  perpendicular L1 L2
  tangent L2 A1
  perpendicular L2 L4
  tangent L5 A2
  parallel L1 L7
  perpendicular L6 L7
  tangent A2 L6
  tangent A1 L3
  parallel L3 L5
  symmetric P3 L1 P15
  symmetric L1 P4 P16
  symmetric L1 P5 P18
  symmetric L1 A1 A3
  symmetric L1 P7 P19
  symmetric L1 P8 P24
  symmetric L1 P9 P23
  symmetric L1 P10 P20
  symmetric L1 A2 A4
  symmetric L1 P12 P21
  dimension "d11_3" distance L4 L7 = 380 (= "meio_viga")
  dimension "d12_3" distance L2 L8 = 5
  dimension "d13_3" angle L5 L6 = 162 (= "180 deg - 18 deg")
  dimension "d14_3" distance P3 P12 = 50
  dimension "d15_3" distance P10 P12 = 105 (= "reto_inf_viga")
  dimension "d16_3" distance P3 P4 = 105 (= "reto_inf_viga")
  dimension "d88" radius A1 = 260
  dimension "d89" radius A2 = 195
loft "Loft1" sketch "Sketch1" + "Sketch2"
work_plane "WorkPlane2" AlongDistance 60 named "d19_3" ExtraOffset 0 named "d20_3"
sketch "Sketch3" plane through (0, 0, 60) normal (0, 0, 1) x axis (1, 0, 0)
  line L1 (0, 52.5) -> (0, 0)
  line L2 (380, 52.5) -> (-380, 52.5)
  point P1 (0, 0)
  point P2 (0, 0)
  point P3 (0, 52.5)
  point P4 (-380, 52.5)
  point P5 (380, 52.5)
  coincident P1 P2
  vertical L1
  horizontal L2
  midpoint P3 L2
  dimension "d21_3" distance P4 P5 = 760 (= "meio_viga * 2")
  dimension "d22_3" distance P2 P3 = 52.5
sketch "Sketch4" plane through (0, 0, 0) normal (0, 1, 0) x axis (1, 0, 0)
  curve K1 (354.3074, 19.8137) -> (-354.3074, 19.8137)
sketch "Sketch5" plane through (0, 0, 60) normal (0, 0, 1) x axis (1, 0, 0)
  line L1 (0, 105) -> (0, 0)
  line L2 (38, 10) -> (-38, 10)
  line L3 (42, 16.9282) -> (38, 10)
  line L4 (4, 79.258) -> (42, 16.9282)
  line L5 (-4, 79.258) -> (4, 79.258)
  line L6 (-42, 16.9282) -> (-4, 79.258)
  line L7 (-38, 10) -> (-42, 16.9282)
  line L8 (0, 52.5) -> (0, 0)
  line L9 (0, 79.258) -> (0, 52.5)
  line L10 (380, 0) -> (-380, 0)
  line L11 (-26.1692, 52.5) -> (0, 52.5)
  line L12 (-10.3385, 88.0718) -> (-48.3385, 25.742)
  line L13 (-48.3385, 25.742) -> (-56.3385, 25.742)
  line L14 (-56.3385, 25.742) -> (-94.3385, 88.0718)
  line L15 (-90.3385, 95) -> (-14.3385, 95)
  line L16 (-94.3385, 88.0718) -> (-90.3385, 95)
  line L17 (-14.3385, 95) -> (-10.3385, 88.0718)
  point P1 (0, 0)
  point P2 (0, 0)
  point P11 (0, 52.5)
  point P12 (0, 52.5)
  point P13 (0, 79.258)
  point P16 (0, 52.5)
  point P3 (0, 105)
  point P4 (-38, 10)
  point P5 (38, 10)
  point P6 (42, 16.9282)
  point P7 (4, 79.258)
  coincident P1 P2
  vertical L1
  perpendicular L1 L2
  parallel L2 L5
  equal L5 L7
  equal L3 L5
  equal L4 L6
  coincident P11 P12
  midpoint L5 P13
  vertical L9
  coincident P11 P16
  perpendicular L8 L11
  dimension "d23_3" distance P2 P3 = 105
  dimension "d24_3" distance P4 P5 = 76
  dimension "d25_3" distance P4 L8 = 38
  dimension "d26_3" distance P5 P6 = 8
  dimension "d27_3" distance P6 P7 = 73
  dimension "d28_3" angle L2 L7 = 120
  dimension "d29_3" distance L2 L10 = 10
  dimension "d32_2" distance L6 L12 = 10
  dimension "d31_2" C-Pattern1-Angle = 360
extrude "Extrude1" cut sketch "Sketch5" profile of L2 L3 L4 L5 L6 L7 L12 L13 L14 L15 L16 L17 against normal blind 110 named "d33_2" and along normal blind 30 named "d37_2"
path_pattern "PathPattern1" PathPatternDelta 916.8 (= "largura * 0.8") named "d36_2"
path_pattern "PathPattern2" PathPatternDelta 916.8 (= "largura * 0.8") named "d40_2"
sketch "Sketch6" plane through (0, 105, 0) normal (0, 1, 0) x axis (-1, 0, 0)
  curve K1 (380, -84.3178) -> (-380, -84.3178)
  line L1 (380, -30.9727) -> (380, -84.3178)
  curve K2 (-380, -30.9727) -> (380, -30.9727)
  line L2 (-380, -84.3178) -> (-380, -30.9727)
  curve K3 (-380, -30.9727) -> (380, -30.9727)
  curve K4 (380, -84.3178) -> (-380, -84.3178)
  line L3 (-370, -81.0686) -> (-370, -27.7235)
  point P10 (-370, -27.7235)
  point P11 (-370, -81.0686)
  coincident K2 P10
  coincident K1 P11
  parallel L2 L3
  dimension "d41_2" distance L2 L3 = 10
sketch "Sketch7" plane through (0, 0, 0) normal (0, -1, 0) x axis (1, 0, 0)
  curve K1 (-380, -95.6023) -> (380, -95.6023)
  line L1 (380, -25.6023) -> (380, -95.6023)
  curve K2 (380, -25.6023) -> (-380, -25.6023)
  line L2 (-380, -95.6023) -> (-380, -25.6023)
  curve K3 (380, -25.6023) -> (-380, -25.6023)
  curve K4 (-380, -95.6023) -> (380, -95.6023)
  line L3 (370, -91.7637) -> (370, -22.4091)
  point P10 (370, -22.4091)
  point P11 (370, -91.7637)
  coincident K3 P10
  coincident K1 P11
  vertical L3
  dimension "d42_2" distance L1 L3 = 10
loft "Loft3" sketch "Sketch6" + "Sketch7"
mirror "Mirror1" mirrorStitchTolerance 0.1 named "d44_1"
sketch "Sketch8" plane through (380, 0, 0) normal (1, 0, 0) x axis (0, 1, 0)
  line L1 (0, -25.6023) -> (5.6059, -25.889)
  line L2 (0, -95.6023) -> (0, -25.6023)
  line L3 (5.3323, -95.0292) -> (0, -95.6023)
  line L4 (105, -30.9727) -> (105, -84.3178)
  line L5 (10, -94.5276) -> (10, -26.1138)
  line L6 (16, -26.4207) -> (16, -93.8828)
  line L7 (89, -30.1544) -> (89, -86.0373)
  line L8 (95, -85.3925) -> (95, -30.4613)
  line L9 (105, -30.9727) -> (5.6059, -25.889)
  line L10 (5.3323, -95.0292) -> (70.8894, -87.9837)
  line L11 (105, -84.3178) -> (70.8894, -87.9837)
  line L12 (70.8894, -87.9837) -> (5.3323, -95.0292)
  line L13 (105, -84.3178) -> (70.8894, -87.9837)
  line L14 (5.6059, -25.889) -> (105, -30.9727)
  point P11 (16, -26.4207)
  point P9 (10, -94.5276)
  point P10 (16, -93.8828)
  point P15 (95, -85.3925)
  point P13 (89, -30.1544)
  point P8 (10, -26.1138)
  point P14 (95, -30.4613)
  vertical L5
  parallel L5 L6
  parallel L6 L7
  vertical L8
  coincident P11 L9
  coincident P9 L10
  coincident P10 L10
  coincident P15 L11
  coincident P13 L9
  coincident L1 P8
  coincident P14 L9
  dimension "d45_1" distance L4 L8 = 10
  dimension "d47_1" distance L7 L8 = 6
  dimension "d48_1" distance L5 L6 = 6
  dimension "d49_1" distance L2 L5 = 10
extrude "Extrude2" add sketch "Sketch8" profile of L5 L6 L7 L8 along normal blind 25 named "d50_2"
mirror "Mirror2" mirrorStitchTolerance 0.1 named "d53_1"
joint "Assemble" alignAngle 270 alignOffsetX -50 (= "x_box") alignOffsetY 0 alignOffsetZ 0
joint "Assemble" alignAngle -210 alignOffsetX 0 alignOffsetY 0 alignOffsetZ 0
joint "Assemble" alignAngle 90 alignOffsetX 0 alignOffsetY 0 alignOffsetZ 0
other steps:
create_component "CreateComponent1"
create_component "CreateComponent2"
create_component "CreateComponent3"
create_component "CreateComponent4"
joint_origin "JointOrigin3"
joint_origin "JointOrigin3"
joint_origin "JointOrigin1"
joint_origin "JointOrigin4"
joint_origin "JointOrigin7"
joint_origin "JointOrigin3"
named bodies: "camara", "camara (Assembly_Perseverance)", "lente_dir", "lente_dir (Assembly_Perseverance)", "sensor_esq", "lente_esq", "sensor_dir (Assembly_Perseverance)", "sensor_esq (Assembly_Perseverance)", "lente_esq (Assembly_Perseverance)", "Body1 (Assembly_Perseverance)"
